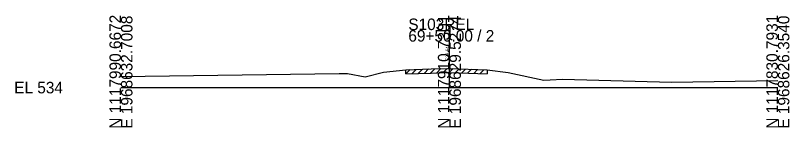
# Model space of a CAD drawing. Extents: x -26 to 163, y -10 to 24518.
# Drawn here: x -25.7 to 162.8, y 17990.3 to 18017.5 of the extents above; entities that cross this region are included whole.
import ezdxf

# ---------------------------------------------------------------- set-up
doc = ezdxf.new("R2010")
doc.units = 0
for name, color, linetype in [('RD_GPK_XS_Cell', 7, 'Continuous'), ('RD_XS_ExGround', 7, 'Continuous'), ('RD_XS_ExPaveRet', 7, 'Continuous'), ('RD_XS_TX_Elev_EX', 7, 'Continuous')]:
    doc.layers.add(name, color=color, linetype=linetype)

msp = doc.modelspace()

# ---------------------------------------------------------------- linework, layer by layer
at = {"layer": 'RD_GPK_XS_Cell'}
for p, q in [((80, 18000), (80, 18013.97)), ((0, 18000), (80, 18000)), ((80, 18000), (160, 18000))]:
    msp.add_line(p, q, dxfattribs=at)
at = {"layer": 'RD_XS_ExGround'}
msp.add_lwpolyline([(0, 18002.66), (53.11, 18003.41), (54.25, 18003.4), (55.18, 18003.44), (59.48, 18002.58), (63.96, 18003.71), (69.41, 18004.35), (75.58, 18004.54), (79.56, 18004.66), (80, 18004.64), (89.19, 18004.32), (94.28, 18003.7), (103.03, 18001.81), (104.53, 18001.88), (107.58, 18002.03), (134.07, 18001.35), (160, 18001.75)], dxfattribs=at)
at = {"layer": 'RD_XS_ExPaveRet'}
for p, q in [((69.41, 18003.35), (70.44, 18004.38)), ((69.41, 18003.35), (69.41, 18004.35)), ((69.41, 18003.35), (75.58, 18003.54)), ((70.91, 18003.4), (71.94, 18004.43)), ((72.41, 18003.44), (73.44, 18004.47)), ((73.91, 18003.49), (74.94, 18004.52)), ((75.41, 18003.53), (76.44, 18004.56)), ((75.58, 18003.54), (79.56, 18003.66)), ((76.91, 18003.58), (77.94, 18004.61)), ((78.41, 18003.62), (79.44, 18004.65)), ((79.56, 18003.66), (80, 18003.64)), ((79.91, 18003.64), (80.88, 18004.61)), ((80, 18003.64), (89.19, 18003.32)), ((81.41, 18003.59), (82.38, 18004.56)), ((82.91, 18003.54), (83.88, 18004.51)), ((84.41, 18003.49), (85.38, 18004.45)), ((85.91, 18003.43), (86.88, 18004.4)), ((87.41, 18003.38), (88.38, 18004.35)), ((89.19, 18004.32), (89.19, 18003.32))]:
    msp.add_line(p, q, dxfattribs=at)

# ---------------------------------------------------------------- texts
at = {"layer": 'RD_GPK_XS_Cell'}
for s, p in [('N 1117990.6672', (0, 17990)), ('E 1968632.7008', (2.8, 17990)), ('N 1117910.7301', (80, 17990)), ('E 1968629.5274', (82.8, 17990)), ('N 1117830.7931', (160, 17990)), ('E 1968626.3540', (162.8, 17990))]:
    msp.add_text(s, height=2.8, rotation=90, dxfattribs=at).set_placement(p)
for s, p in [('S103REL', (70, 18013.97)), ('69+50.00 / 2', (70, 18011.17)), ('EL 534', (-26, 17998.6))]:
    msp.add_text(s, height=2.8, dxfattribs=at).set_placement(p)
at = {"layer": 'RD_XS_TX_Elev_EX'}
msp.add_text('538.64', height=0.8, rotation=90, dxfattribs=at).set_placement((79.9, 18006.64))

doc.saveas('drawing.dxf')
